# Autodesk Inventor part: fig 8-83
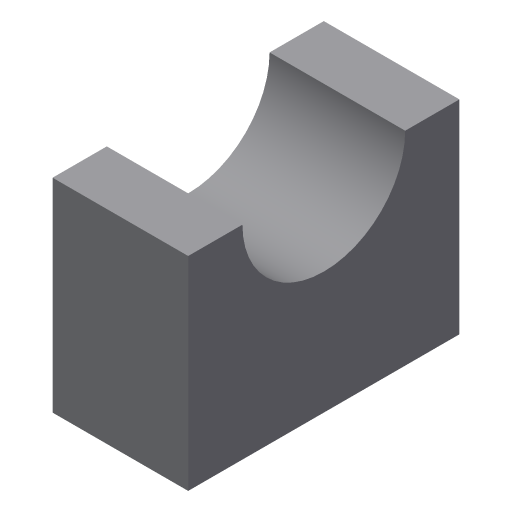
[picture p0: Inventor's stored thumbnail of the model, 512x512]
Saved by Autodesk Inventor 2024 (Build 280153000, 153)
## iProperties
Shininess: 77.0
Length Units: 11269
Angle Units: 11279
Time Units: 11290
Mass Units: 11283
Length Display Precision: 3
Angle Display Precision: 2
Created: 2002-01
Part Number: fig 8-83
Document SubType Name: Modeling
Designer: ***
Density: 1 g/cm^3
Material: Generic
Appearance: Default
Density: 0.0
Volumn: 0.0
Area: 0.0
PropertySet Name: Model Information
Control State: 0
Master: False
Checked Out: False
Author: ***
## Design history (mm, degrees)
sketch "Sketch5"
  geometry: L1 (-22.226, 10.275)-(-14.226, 10.275); L2 (9.774, 10.275)-(17.774, 10.275); L3 (17.774, 10.275)-(17.774, -19.725); L4 (17.774, -19.725)-(-22.226, -19.725); L5 (-22.226, -19.725)-(-22.226, 10.275); A1 r 12 centre (-2.226, 10.275) between (-14.226, 10.275) and (9.774, 10.275)
  constraints: 10 end point, 2 equal length, 2 parallel, 2 point on circle, 1 centre point, 1 collinear, 1 horizontal, 1 perpendicular, 1 point on line
  dimensions: "d7" = 40 distance of L3.end L4.end; "d8" = 30 distance of L2.end L3.end; "d9" = 12 radius of A1
extrude "Extrusion2" new body sketch "Sketch5" distance "d10" = 20; taper "d11" = 0 deg
workplane "Work Plane3"
sketch "Sketch6"
  geometry: L1 (19.321, -18.091)-(12.314, -18.091); L2 (12.314, -18.091)-(12.314, -11.217); L3 (12.314, -11.217)-(7.026, -11.217); L4 (7.026, -11.217)-(7.026, 7.425); L5 (7.026, 7.425)-(7.026, 14.035); L6 (7.026, 14.035)-(-10.029, 14.035)
  constraints: 12 end point, 4 parallel, 1 horizontal, 1 perpendicular
split "Split5" sketch "Sketch6"
body "Solid1"
other parameters: "d12" = 15
